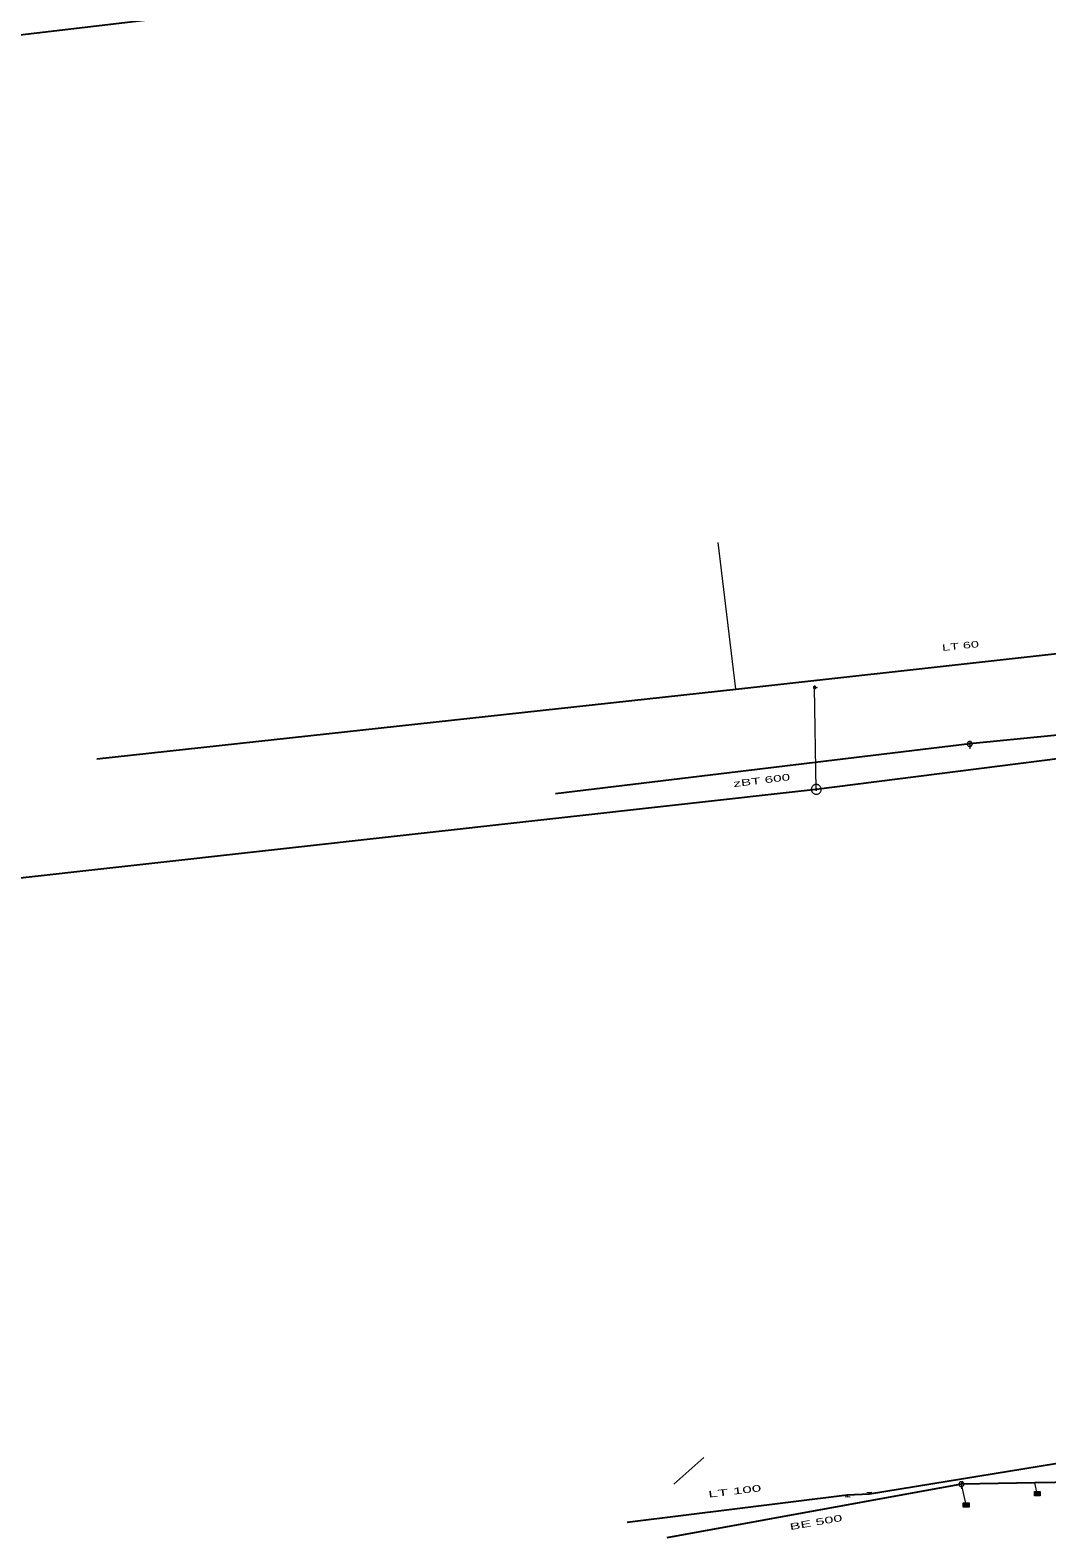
# Model space of a CAD drawing. Extents: x -687468 to -685917, y -974192 to -973456.
# Drawn here: x -686944.4 to -686841, y -973730.1 to -973576.9 of the extents above; entities that cross this region are included whole.
import ezdxf
from ezdxf.enums import TextEntityAlignment as Align

# ---------------------------------------------------------------- set-up
doc = ezdxf.new("R2010")
doc.units = 0
doc.header["$LTSCALE"] = 0.27
for name, color, linetype, lineweight in [('1', 7, 'Continuous', 13), ('11', 7, 'Continuous', 13), ('13', 7, 'Continuous', 13), ('14', 7, 'Continuous', 25), ('17', 7, 'Continuous', 25), ('22', 7, 'Continuous', 13), ('34', 7, 'Continuous', 13), ('47', 7, 'Continuous', 13), ('9', 7, 'Continuous', 13)]:
    doc.layers.add(name, color=color, linetype=linetype, lineweight=lineweight)

msp = doc.modelspace()

# ---------------------------------------------------------------- linework, layer by layer
at = {"layer": '11'}
for p, q in [((-686875.89, -973721.97), (-686878.96, -973724.68)), ((-686849.25, -973726.78), (-686849.73, -973724.67)), ((-686842.02, -973725.63), (-686842.258, -973724.526))]:
    msp.add_line(p, q, dxfattribs=at)
at = {"layer": '13'}
msp.add_line((-686872.671, -973643.865), (-686874.464, -973628.946), dxfattribs=at)
at = {"layer": '14', "lineweight": 13}
for p, q in [((-686864.483, -973654.051), (-686864.649, -973643.689)), ((-686861.337, -973725.804), (-686861.299, -973725.979)), ((-686859.074, -973725.682), (-686859.089, -973725.5))]:
    msp.add_line(p, q, dxfattribs=at)
at = {"layer": '14'}
for p, q in [((-686826.007, -973647.121), (-686848.883, -973649.437)), ((-686848.883, -973649.437), (-686890.976, -973654.512)), ((-686849.73, -973724.67), (-686879.68, -973730.129))]:
    msp.add_line(p, q, dxfattribs=at)
msp.add_lwpolyline([(-686811.199, -973724.039), (-686842.258, -973724.526), (-686849.73, -973724.67)], dxfattribs=at)
at = {"layer": '17'}
for p, q in [((-686760.428, -973640.909), (-686864.483, -973654.051)), ((-686864.483, -973654.051), (-687064.409, -973676.368))]:
    msp.add_line(p, q, dxfattribs=at)
for points in [[(-686645.309, -973464.46), (-686646.34, -973464.75), (-686680.188, -973471.317), (-686771.188, -973470.317), (-686761.188, -973557.317), (-686894.188, -973571.317), (-686953.188, -973578.317), (-686955.188, -973554.317), (-687116.188, -973577.317), (-687229.188, -973601.317), (-687468.188, -973649.317), (-687458.188, -973700.317)], [(-686937.575, -973650.962), (-686872.671, -973643.864), (-686761.239, -973631.509)], [(-686778.16, -973716.008), (-686787.234, -973721.504), (-686796.6, -973724.188), (-686817.64, -973721.881), (-686819.859, -973721.829), (-686837.05, -973722.085), (-686859.074, -973725.682), (-686861.337, -973725.804), (-686883.709, -973728.57)]]:
    msp.add_lwpolyline(points, dxfattribs=at)
at = {"layer": '22'}
for p, q in [((-686848.882, -973649.185), (-686848.883, -973649.929)), ((-686849.729, -973724.418), (-686849.73, -973725.162)), ((-686849.545, -973726.709), (-686848.947, -973726.709)), ((-686842.315, -973725.559), (-686841.717, -973725.559)), ((-686842.315, -973725.705), (-686841.717, -973725.705)), ((-686849.545, -973726.855), (-686848.947, -973726.855))]:
    msp.add_line(p, q, dxfattribs=at)
for points in [[(-686848.631, -973649.437), (-686848.632, -973649.411), (-686848.636, -973649.385), (-686848.642, -973649.359), (-686848.652, -973649.335), (-686848.664, -973649.311), (-686848.678, -973649.289), (-686848.695, -973649.268), (-686848.713, -973649.25), (-686848.734, -973649.233), (-686848.756, -973649.219), (-686848.78, -973649.207), (-686848.804, -973649.197), (-686848.83, -973649.191), (-686848.856, -973649.187), (-686848.882, -973649.185), (-686848.908, -973649.186), (-686848.934, -973649.19), (-686848.96, -973649.196), (-686848.985, -973649.206), (-686849.008, -973649.218), (-686849.03, -973649.232), (-686849.051, -973649.249), (-686849.069, -973649.267), (-686849.086, -973649.288), (-686849.1, -973649.31), (-686849.112, -973649.334), (-686849.122, -973649.358), (-686849.129, -973649.384), (-686849.133, -973649.41), (-686849.135, -973649.436), (-686849.134, -973649.462), (-686849.13, -973649.488), (-686849.123, -973649.514), (-686849.113, -973649.539), (-686849.101, -973649.562), (-686849.087, -973649.584), (-686849.07, -973649.605), (-686849.052, -973649.623), (-686849.031, -973649.64), (-686849.009, -973649.654), (-686848.986, -973649.666), (-686848.961, -973649.676), (-686848.935, -973649.683), (-686848.909, -973649.687), (-686848.883, -973649.689), (-686848.857, -973649.688), (-686848.831, -973649.684), (-686848.805, -973649.677), (-686848.781, -973649.667), (-686848.757, -973649.655), (-686848.735, -973649.641), (-686848.714, -973649.624), (-686848.696, -973649.606), (-686848.679, -973649.585), (-686848.665, -973649.563), (-686848.653, -973649.54), (-686848.643, -973649.515), (-686848.637, -973649.489), (-686848.633, -973649.463)], [(-686849.478, -973724.67), (-686849.479, -973724.644), (-686849.483, -973724.618), (-686849.489, -973724.592), (-686849.499, -973724.568), (-686849.511, -973724.544), (-686849.525, -973724.522), (-686849.542, -973724.501), (-686849.56, -973724.483), (-686849.581, -973724.466), (-686849.603, -973724.452), (-686849.627, -973724.44), (-686849.651, -973724.43), (-686849.677, -973724.424), (-686849.703, -973724.42), (-686849.729, -973724.418), (-686849.755, -973724.419), (-686849.781, -973724.423), (-686849.807, -973724.429), (-686849.832, -973724.439), (-686849.855, -973724.451), (-686849.877, -973724.465), (-686849.898, -973724.482), (-686849.916, -973724.5), (-686849.933, -973724.521), (-686849.947, -973724.543), (-686849.959, -973724.567), (-686849.969, -973724.591), (-686849.976, -973724.617), (-686849.98, -973724.643), (-686849.982, -973724.669), (-686849.981, -973724.695), (-686849.977, -973724.721), (-686849.97, -973724.747), (-686849.96, -973724.772), (-686849.948, -973724.795), (-686849.934, -973724.817), (-686849.917, -973724.838), (-686849.899, -973724.856), (-686849.878, -973724.873), (-686849.856, -973724.887), (-686849.833, -973724.899), (-686849.808, -973724.909), (-686849.782, -973724.916), (-686849.756, -973724.92), (-686849.73, -973724.922), (-686849.704, -973724.921), (-686849.678, -973724.917), (-686849.652, -973724.91), (-686849.628, -973724.9), (-686849.604, -973724.888), (-686849.582, -973724.874), (-686849.561, -973724.857), (-686849.543, -973724.839), (-686849.526, -973724.818), (-686849.512, -973724.796), (-686849.5, -973724.773), (-686849.49, -973724.748), (-686849.484, -973724.722), (-686849.48, -973724.696)], [(-686849.545, -973726.563), (-686848.947, -973726.563), (-686848.947, -973727), (-686849.545, -973727)], [(-686842.315, -973725.413), (-686841.717, -973725.413), (-686841.717, -973725.85), (-686842.315, -973725.85)]]:
    msp.add_lwpolyline(points, close=True, dxfattribs=at)
at = {"layer": '34'}
for p, q in [((-686861.051, -973725.99), (-686861.546, -973725.967)), ((-686859.336, -973725.511), (-686858.841, -973725.488))]:
    msp.add_line(p, q, dxfattribs=at)
at = {"layer": '47'}
for points in [[(-686863.984, -973654.012), (-686863.991, -973653.96), (-686864.003, -973653.909), (-686864.021, -973653.86), (-686864.043, -973653.813), (-686864.07, -973653.768), (-686864.102, -973653.726), (-686864.138, -973653.689), (-686864.178, -973653.655), (-686864.221, -973653.625), (-686864.267, -973653.6), (-686864.315, -973653.579), (-686864.366, -973653.565), (-686864.417, -973653.555), (-686864.469, -973653.551), (-686864.521, -973653.552), (-686864.573, -973653.559), (-686864.624, -973653.571), (-686864.674, -973653.589), (-686864.72, -973653.611), (-686864.765, -973653.638), (-686864.807, -973653.67), (-686864.845, -973653.706), (-686864.879, -973653.746), (-686864.909, -973653.789), (-686864.933, -973653.835), (-686864.954, -973653.883), (-686864.969, -973653.934), (-686864.978, -973653.985), (-686864.982, -973654.037), (-686864.981, -973654.089), (-686864.974, -973654.141), (-686864.962, -973654.192), (-686864.945, -973654.242), (-686864.922, -973654.288), (-686864.895, -973654.333), (-686864.864, -973654.375), (-686864.828, -973654.413), (-686864.788, -973654.447), (-686864.744, -973654.477), (-686864.698, -973654.501), (-686864.65, -973654.522), (-686864.6, -973654.537), (-686864.548, -973654.546), (-686864.496, -973654.55), (-686864.444, -973654.549), (-686864.392, -973654.542), (-686864.341, -973654.53), (-686864.292, -973654.513), (-686864.245, -973654.49), (-686864.2, -973654.463), (-686864.158, -973654.432), (-686864.121, -973654.396), (-686864.087, -973654.356), (-686864.057, -973654.312), (-686864.032, -973654.266), (-686864.011, -973654.218), (-686863.997, -973654.168), (-686863.987, -973654.116), (-686863.983, -973654.064)], [(-686864.401, -973654.044), (-686864.401, -973654.035), (-686864.404, -973654.027), (-686864.407, -973654.02), (-686864.41, -973654.012), (-686864.415, -973654.004), (-686864.42, -973653.998), (-686864.426, -973653.991), (-686864.432, -973653.985), (-686864.44, -973653.981), (-686864.447, -973653.977), (-686864.455, -973653.973), (-686864.464, -973653.971), (-686864.472, -973653.969), (-686864.48, -973653.968), (-686864.489, -973653.969), (-686864.498, -973653.969), (-686864.506, -973653.972), (-686864.513, -973653.975), (-686864.521, -973653.978), (-686864.529, -973653.983), (-686864.535, -973653.988), (-686864.542, -973653.994), (-686864.548, -973654), (-686864.553, -973654.008), (-686864.556, -973654.015), (-686864.56, -973654.023), (-686864.562, -973654.032), (-686864.564, -973654.04), (-686864.565, -973654.048), (-686864.564, -973654.057), (-686864.564, -973654.066), (-686864.561, -973654.074), (-686864.558, -973654.081), (-686864.555, -973654.089), (-686864.55, -973654.097), (-686864.546, -973654.104), (-686864.539, -973654.11), (-686864.533, -973654.116), (-686864.525, -973654.121), (-686864.518, -973654.124), (-686864.51, -973654.128), (-686864.501, -973654.13), (-686864.493, -973654.132), (-686864.485, -973654.133), (-686864.476, -973654.132), (-686864.467, -973654.132), (-686864.459, -973654.129), (-686864.452, -973654.126), (-686864.444, -973654.123), (-686864.436, -973654.118), (-686864.429, -973654.114), (-686864.423, -973654.107), (-686864.417, -973654.101), (-686864.413, -973654.093), (-686864.409, -973654.086), (-686864.405, -973654.078), (-686864.403, -973654.069), (-686864.401, -973654.061), (-686864.4, -973654.053)]]:
    msp.add_lwpolyline(points, close=True, dxfattribs=at)
at = {"layer": '9'}
msp.add_line((-686864.522, -973643.689), (-686864.397, -973643.689), dxfattribs=at)
for points in [[(-686864.649, -973643.815), (-686864.636, -973643.814), (-686864.623, -973643.812), (-686864.61, -973643.809), (-686864.598, -973643.804), (-686864.586, -973643.798), (-686864.575, -973643.791), (-686864.565, -973643.783), (-686864.555, -973643.773), (-686864.547, -973643.763), (-686864.54, -973643.752), (-686864.534, -973643.74), (-686864.529, -973643.728), (-686864.526, -973643.715), (-686864.524, -973643.702), (-686864.522, -973643.689), (-686864.523, -973643.676), (-686864.525, -973643.663), (-686864.528, -973643.65), (-686864.533, -973643.638), (-686864.539, -973643.626), (-686864.546, -973643.615), (-686864.554, -973643.605), (-686864.564, -973643.595), (-686864.574, -973643.587), (-686864.585, -973643.58), (-686864.597, -973643.574), (-686864.609, -973643.569), (-686864.622, -973643.566), (-686864.635, -973643.564), (-686864.648, -973643.563), (-686864.661, -973643.563), (-686864.674, -973643.565), (-686864.687, -973643.568), (-686864.699, -973643.573), (-686864.711, -973643.579), (-686864.722, -973643.586), (-686864.732, -973643.594), (-686864.742, -973643.604), (-686864.75, -973643.614), (-686864.757, -973643.625), (-686864.763, -973643.637), (-686864.768, -973643.649), (-686864.771, -973643.662), (-686864.773, -973643.675), (-686864.775, -973643.688), (-686864.774, -973643.701), (-686864.772, -973643.714), (-686864.769, -973643.727), (-686864.764, -973643.739), (-686864.758, -973643.751), (-686864.751, -973643.762), (-686864.743, -973643.772), (-686864.733, -973643.782), (-686864.723, -973643.79), (-686864.712, -973643.797), (-686864.7, -973643.803), (-686864.688, -973643.808), (-686864.675, -973643.811), (-686864.662, -973643.813)], [(-686864.649, -973643.795), (-686864.638, -973643.795), (-686864.627, -973643.793), (-686864.616, -973643.79), (-686864.606, -973643.786), (-686864.596, -973643.781), (-686864.587, -973643.775), (-686864.578, -973643.768), (-686864.57, -973643.76), (-686864.563, -973643.751), (-686864.557, -973643.742), (-686864.552, -973643.732), (-686864.548, -973643.722), (-686864.545, -973643.711), (-686864.543, -973643.7), (-686864.543, -973643.689), (-686864.542, -973643.678), (-686864.544, -973643.667), (-686864.547, -973643.656), (-686864.551, -973643.646), (-686864.556, -973643.636), (-686864.562, -973643.627), (-686864.569, -973643.618), (-686864.577, -973643.61), (-686864.586, -973643.603), (-686864.595, -973643.597), (-686864.605, -973643.592), (-686864.615, -973643.588), (-686864.626, -973643.585), (-686864.637, -973643.583), (-686864.648, -973643.583), (-686864.659, -973643.582), (-686864.67, -973643.584), (-686864.681, -973643.587), (-686864.691, -973643.591), (-686864.701, -973643.596), (-686864.71, -973643.602), (-686864.719, -973643.609), (-686864.727, -973643.617), (-686864.734, -973643.626), (-686864.74, -973643.635), (-686864.745, -973643.645), (-686864.749, -973643.655), (-686864.752, -973643.666), (-686864.754, -973643.677), (-686864.755, -973643.688), (-686864.755, -973643.699), (-686864.753, -973643.71), (-686864.75, -973643.721), (-686864.746, -973643.731), (-686864.741, -973643.741), (-686864.735, -973643.75), (-686864.728, -973643.759), (-686864.72, -973643.767), (-686864.711, -973643.774), (-686864.702, -973643.78), (-686864.692, -973643.785), (-686864.682, -973643.789), (-686864.671, -973643.792), (-686864.66, -973643.794)], [(-686864.649, -973643.776), (-686864.64, -973643.775), (-686864.631, -973643.774), (-686864.622, -973643.771), (-686864.614, -973643.768), (-686864.606, -973643.764), (-686864.598, -973643.759), (-686864.591, -973643.753), (-686864.585, -973643.747), (-686864.579, -973643.74), (-686864.574, -973643.732), (-686864.57, -973643.724), (-686864.567, -973643.716), (-686864.564, -973643.707), (-686864.563, -973643.698), (-686864.561, -973643.689), (-686864.562, -973643.68), (-686864.563, -973643.671), (-686864.566, -973643.662), (-686864.569, -973643.654), (-686864.573, -973643.646), (-686864.578, -973643.638), (-686864.584, -973643.631), (-686864.59, -973643.625), (-686864.597, -973643.619), (-686864.605, -973643.614), (-686864.613, -973643.61), (-686864.621, -973643.607), (-686864.63, -973643.604), (-686864.639, -973643.603), (-686864.648, -973643.602), (-686864.657, -973643.602), (-686864.666, -973643.603), (-686864.675, -973643.606), (-686864.683, -973643.609), (-686864.691, -973643.613), (-686864.699, -973643.618), (-686864.706, -973643.624), (-686864.712, -973643.63), (-686864.718, -973643.637), (-686864.723, -973643.645), (-686864.727, -973643.653), (-686864.73, -973643.661), (-686864.733, -973643.67), (-686864.734, -973643.679), (-686864.736, -973643.688), (-686864.735, -973643.697), (-686864.734, -973643.706), (-686864.731, -973643.715), (-686864.728, -973643.723), (-686864.724, -973643.731), (-686864.719, -973643.739), (-686864.713, -973643.746), (-686864.707, -973643.752), (-686864.7, -973643.758), (-686864.692, -973643.763), (-686864.684, -973643.767), (-686864.676, -973643.77), (-686864.667, -973643.773), (-686864.658, -973643.774)], [(-686864.649, -973643.756), (-686864.642, -973643.756), (-686864.635, -973643.754), (-686864.628, -973643.753), (-686864.622, -973643.75), (-686864.616, -973643.747), (-686864.61, -973643.743), (-686864.604, -973643.739), (-686864.599, -973643.734), (-686864.595, -973643.728), (-686864.591, -973643.722), (-686864.588, -973643.716), (-686864.585, -973643.71), (-686864.584, -973643.703), (-686864.582, -973643.696), (-686864.581, -973643.689), (-686864.581, -973643.682), (-686864.583, -973643.675), (-686864.584, -973643.668), (-686864.587, -973643.662), (-686864.59, -973643.655), (-686864.594, -973643.65), (-686864.598, -973643.644), (-686864.603, -973643.639), (-686864.609, -973643.635), (-686864.615, -973643.631), (-686864.621, -973643.628), (-686864.627, -973643.625), (-686864.634, -973643.623), (-686864.641, -973643.622), (-686864.648, -973643.622), (-686864.655, -973643.621), (-686864.662, -973643.622), (-686864.669, -973643.624), (-686864.675, -973643.627), (-686864.682, -973643.63), (-686864.687, -973643.634), (-686864.693, -973643.638), (-686864.698, -973643.643), (-686864.702, -973643.649), (-686864.706, -973643.654), (-686864.709, -973643.661), (-686864.712, -973643.667), (-686864.714, -973643.674), (-686864.715, -973643.681), (-686864.716, -973643.688), (-686864.716, -973643.695), (-686864.715, -973643.702), (-686864.713, -973643.709), (-686864.71, -973643.715), (-686864.707, -973643.721), (-686864.703, -973643.727), (-686864.699, -973643.733), (-686864.694, -973643.738), (-686864.688, -973643.742), (-686864.683, -973643.746), (-686864.676, -973643.749), (-686864.67, -973643.752), (-686864.663, -973643.753), (-686864.656, -973643.755)], [(-686864.649, -973643.736), (-686864.644, -973643.736), (-686864.639, -973643.735), (-686864.634, -973643.734), (-686864.63, -973643.732), (-686864.625, -973643.73), (-686864.621, -973643.727), (-686864.618, -973643.724), (-686864.614, -973643.72), (-686864.611, -973643.717), (-686864.608, -973643.713), (-686864.606, -973643.708), (-686864.604, -973643.704), (-686864.603, -973643.699), (-686864.602, -973643.694), (-686864.602, -973643.689), (-686864.601, -973643.684), (-686864.602, -973643.679), (-686864.603, -973643.674), (-686864.605, -973643.67), (-686864.607, -973643.665), (-686864.61, -973643.661), (-686864.613, -973643.657), (-686864.617, -973643.654), (-686864.62, -973643.651), (-686864.624, -973643.648), (-686864.629, -973643.646), (-686864.633, -973643.644), (-686864.638, -973643.643), (-686864.643, -973643.642), (-686864.648, -973643.642), (-686864.653, -973643.641), (-686864.658, -973643.642), (-686864.663, -973643.643), (-686864.667, -973643.645), (-686864.672, -973643.647), (-686864.676, -973643.65), (-686864.68, -973643.653), (-686864.683, -973643.656), (-686864.686, -973643.66), (-686864.689, -973643.664), (-686864.691, -973643.669), (-686864.693, -973643.673), (-686864.694, -973643.678), (-686864.695, -973643.683), (-686864.696, -973643.688), (-686864.696, -973643.693), (-686864.695, -973643.698), (-686864.694, -973643.703), (-686864.692, -973643.707), (-686864.69, -973643.712), (-686864.687, -973643.716), (-686864.684, -973643.719), (-686864.681, -973643.723), (-686864.677, -973643.726), (-686864.673, -973643.729), (-686864.668, -973643.731), (-686864.664, -973643.733), (-686864.659, -973643.734), (-686864.654, -973643.735)], [(-686864.649, -973643.716), (-686864.646, -973643.716), (-686864.643, -973643.716), (-686864.641, -973643.715), (-686864.638, -973643.714), (-686864.635, -973643.713), (-686864.633, -973643.711), (-686864.631, -973643.709), (-686864.629, -973643.707), (-686864.627, -973643.705), (-686864.625, -973643.703), (-686864.624, -973643.7), (-686864.623, -973643.697), (-686864.622, -973643.695), (-686864.622, -973643.692), (-686864.622, -973643.689), (-686864.621, -973643.686), (-686864.621, -973643.683), (-686864.622, -973643.68), (-686864.623, -973643.678), (-686864.624, -973643.675), (-686864.626, -973643.673), (-686864.628, -973643.67), (-686864.63, -973643.668), (-686864.632, -973643.667), (-686864.634, -973643.665), (-686864.637, -973643.664), (-686864.64, -973643.663), (-686864.642, -973643.662), (-686864.645, -973643.662), (-686864.648, -973643.661), (-686864.651, -973643.661), (-686864.654, -973643.661), (-686864.657, -973643.662), (-686864.659, -973643.663), (-686864.662, -973643.664), (-686864.664, -973643.666), (-686864.667, -973643.667), (-686864.669, -973643.669), (-686864.67, -973643.672), (-686864.672, -973643.674), (-686864.673, -973643.677), (-686864.674, -973643.679), (-686864.675, -973643.682), (-686864.675, -973643.685), (-686864.677, -973643.688), (-686864.676, -973643.691), (-686864.676, -973643.694), (-686864.675, -973643.696), (-686864.674, -973643.699), (-686864.673, -973643.702), (-686864.671, -973643.704), (-686864.67, -973643.706), (-686864.668, -973643.708), (-686864.665, -973643.71), (-686864.663, -973643.712), (-686864.66, -973643.713), (-686864.658, -973643.714), (-686864.655, -973643.715), (-686864.652, -973643.715)], [(-686864.649, -973643.697), (-686864.648, -973643.697), (-686864.647, -973643.697), (-686864.647, -973643.696), (-686864.646, -973643.696), (-686864.645, -973643.696), (-686864.644, -973643.695), (-686864.644, -973643.695), (-686864.643, -973643.694), (-686864.643, -973643.694), (-686864.642, -973643.693), (-686864.642, -973643.692), (-686864.642, -973643.691), (-686864.641, -973643.691), (-686864.641, -973643.69), (-686864.641, -973643.689), (-686864.641, -973643.688), (-686864.641, -973643.687), (-686864.641, -973643.687), (-686864.641, -973643.686), (-686864.641, -973643.685), (-686864.642, -973643.684), (-686864.642, -973643.684), (-686864.643, -973643.683), (-686864.643, -973643.683), (-686864.644, -973643.682), (-686864.645, -973643.682), (-686864.646, -973643.681), (-686864.646, -973643.681), (-686864.647, -973643.681), (-686864.648, -973643.681), (-686864.649, -973643.681), (-686864.65, -973643.681), (-686864.65, -973643.681), (-686864.651, -973643.681), (-686864.652, -973643.681), (-686864.653, -973643.682), (-686864.653, -973643.682), (-686864.654, -973643.683), (-686864.654, -973643.683), (-686864.655, -973643.684), (-686864.655, -973643.685), (-686864.656, -973643.686), (-686864.656, -973643.686), (-686864.656, -973643.687), (-686864.657, -973643.688), (-686864.657, -973643.689), (-686864.657, -973643.69), (-686864.657, -973643.69), (-686864.656, -973643.691), (-686864.656, -973643.692), (-686864.655, -973643.693), (-686864.655, -973643.693), (-686864.654, -973643.694), (-686864.654, -973643.694), (-686864.653, -973643.695), (-686864.652, -973643.695), (-686864.651, -973643.695), (-686864.651, -973643.696), (-686864.65, -973643.696)]]:
    msp.add_lwpolyline(points, close=True, dxfattribs=at)
msp.add_lwpolyline([(-686864.431, -973643.658), (-686864.397, -973643.689), (-686864.432, -973643.72)], dxfattribs=at)

# ---------------------------------------------------------------- texts
at = {"layer": '1'}
for s, rotation, width, p in [('LT 60 ', 6, 1.65, (-686849.591, -973639.769)), ('zBT 600 ', 7, 1.75, (-686869.768, -973653.44)), ('LT 100', 7, 1.95, (-686872.725, -973725.712)), ('BE 500', 10, 1.85, (-686864.451, -973728.873))]:
    msp.add_text(s, height=0.6667, rotation=rotation, dxfattribs=dict(at, width=width)).set_placement(p, align=Align.CENTER)

doc.saveas('drawing.dxf')
